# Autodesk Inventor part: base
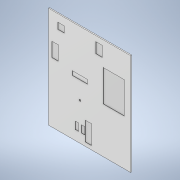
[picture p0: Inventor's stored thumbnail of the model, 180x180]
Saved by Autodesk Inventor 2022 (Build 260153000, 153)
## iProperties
Created: 2021-06
Part Number: base
Material: PC/ABS Plastic
Document SubType Name: Modeling
Designer: Chimms
Density: 0.357273 g/cm^3
Appearance: Smooth - White
Author: Chimms
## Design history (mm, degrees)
sketch "Sketch1"
  geometry: L1 (0, 0)-(150, 0); L2 (150, 0)-(150, -420); L3 (150, -420)-(0, -420); L4 (0, -420)-(0, 0)
  constraints: 8 end point, 2 parallel, 1 horizontal, 1 perpendicular
  dimensions: "d0" = 150 distance of L2.end L3.end; "d1" = 420 distance of L1.end L2.end
extrude "Extrusion1" new body sketch "Sketch1" distance "d2" = 5; taper "d3" = 0 deg
sketch "Sketch2"
  geometry: L1 (150, 0)-(0, 0) reference; L2 (150, 0)-(200, 0); L3 (200, 0)-(200, -420); L4 (200, -420)-(150, -420); L5 (150, -420)-(150, 0)
  constraints: 8 end point, 2 parallel, 1 horizontal, 1 perpendicular
  dimensions: "d4" = 50 distance of L3.end L4.end
extrude "Extrusion2" join sketch "Sketch2" distance "d5" = 5; taper "d6" = 0 deg
sketch "Sketch3"
  geometry: L1 (200, -420)-(200, 0) reference; L2 (200, 0)-(230, 0); L3 (230, 0)-(230, -420); L4 (230, -420)-(200, -420); L5 (200, -420)-(200, 0); 2 further points
  constraints: 8 end point, 2 parallel, 1 horizontal, 1 perpendicular
  dimensions: "d7" = 30 distance of L3.end L4.end
extrude "Extrusion3" join sketch "Sketch3" distance "d8" = 5; taper "d9" = 0 deg
sketch "Sketch4"
  geometry: L1 (0, -420)-(230, -420) reference; L2 (115, -420)-(115, -360); L3 (115, -360)-(122.25, -360); L4 (122.25, -360)-(122.25, -350); L5 (122.25, -350)-(132.25, -350); L6 (132.25, -350)-(142.25, -350); L7 (142.25, -350)-(142.25, -370); L8 (142.25, -370)-(122.25, -370); L9 (122.25, -370)-(122.25, -360); L10 (115, -360)-(107.75, -360); L11 (107.75, -360)-(107.75, -370); L12 (107.75, -370)-(87.75, -370); L13 (87.75, -370)-(87.75, -350); L14 (87.75, -350)-(107.75, -350); L15 (107.75, -350)-(107.75, -360); 1 further point
  constraints: 28 end point, 7 perpendicular, 5 point on line, 2 horizontal, 1 midpoint, 1 vertical
  dimensions: "d10" = 60 distance of L2.start L2.end; "d11" = 7.25 distance of L2.end L3.end; "d12" = 10 distance of L3.end L4.end; "d13" = 10 distance of L4.end L5.end; "d14" = 10 distance of L5.end L6.end; "d15" = 20 distance of L6.end L7.end; "d16" = 7.25 distance of L2.end L10.end; "d17" = 10 distance of L10.end L11.end; "d18" = 20 distance of L11.end L12.end
extrude "Extrusion4" cut sketch "Sketch4" distance "d19" = 2; taper "d20" = 0 deg
sketch "Sketch5"
  geometry: L1 (0, -420)-(230, -420) reference; L2 (115, -420)-(115, -220); L3 (115, -220)-(151, -220); L4 (151, -220)-(151, -200); L5 (151, -200)-(79, -200); L6 (79, -200)-(79, -220); L7 (79, -220)-(115, -220); 1 further point
  constraints: 12 end point, 3 perpendicular, 2 vertical, 1 midpoint
  dimensions: "d21" = 200 distance of L2.start L2.end; "d22" = 36 distance of L2.end L3.end; "d23" = 20 distance of L3.end L4.end; "d24" = 72 distance of L4.end L5.end; "d25" = 20 distance of L5.end L6.end
extrude "Extrusion5" cut sketch "Sketch5" distance "d26" = 2; taper "d27" = 0 deg
sketch "Sketch6"
  geometry: L1 (79, -200)-(151, -200) reference; L2 (115, -200)-(115, -50); L3 (230, 0)-(0, 0) reference; L4 (115, -50)-(190, -50); L5 (190, -50)-(190, -75); L6 (190, -75)-(220, -75); L7 (220, -75)-(220, -25); L8 (220, -25)-(190, -25); L9 (190, -25)-(190, -50); L10 (115, -50)-(40, -50); L11 (40, -50)-(40, -65); L12 (40, -65)-(10, -65); L13 (10, -65)-(10, -35); L14 (10, -35)-(40, -35); L15 (40, -35)-(40, -50)
  constraints: 26 end point, 12 perpendicular, 3 point on line, 1 midpoint
  dimensions: "d28" = 150 distance of L2.start L2.end; "d29" = 75 distance of L2.end L4.end; "d30" = 25 distance of L4.end L5.end; "d31" = 30 distance of L5.end L6.end; "d32" = 50 distance of L6.end L7.end; "d33" = 75 distance of L2.end L10.end; "d34" = 15 distance of L10.end L11.end; "d35" = 30 distance of L11.end L12.end; "d36" = 30 distance of L12.end L13.end
extrude "Extrusion6" cut sketch "Sketch6" distance "d37" = 2; taper "d38" = 0 deg
sketch "Sketch7"
  geometry: L1 (0, 0)-(0, -420) reference; L2 (0, 0)-(-35, 0); L3 (-35, 0)-(-35, -420); L4 (-35, -420)-(0, -420); L5 (0, -420)-(0, 0); 1 further point
  constraints: 8 end point, 2 parallel, 1 horizontal, 1 perpendicular
  dimensions: "d39" = 35 distance of L4.end L3.end
extrude "Extrusion7" join sketch "Sketch7" distance "d40" = 5; taper "d41" = 0 deg
sketch "Sketch8"
  geometry: L1 (-35, 0)-(230, 0) reference; L2 (230, 0)-(275, 0); L3 (275, 0)-(275, -420); L4 (275, -420)-(230, -420); L5 (230, -420)-(230, 0); 1 further point
  constraints: 8 end point, 2 parallel, 1 horizontal, 1 perpendicular
  dimensions: "d42" = 45 distance of L3.end L4.end; "d43" = 420 distance of L2.end L3.end
extrude "Extrusion8" join sketch "Sketch8" distance "d44" = 5; taper "d45" = 0 deg
sketch "Sketch9"
  geometry: L1 (275, -420)-(-35, -420) reference; L2 (275, -420)-(325, -420); L3 (325, -420)-(325, 0); L4 (325, 0)-(275, 0); L5 (275, 0)-(275, -420); 1 further point
  constraints: 8 end point, 2 parallel, 1 horizontal, 1 perpendicular
  dimensions: "d46" = 50 distance of L4.end L3.end
extrude "Extrusion9" join sketch "Sketch9" distance "d47" = 5; taper "d48" = 0 deg
sketch "Sketch10"
  geometry: L1 (325.31, -263.749)-(225.31, -263.749); L2 (225.31, -263.749)-(225.31, -113.749); L3 (225.31, -113.749)-(325.31, -113.749); L4 (325.31, -113.749)-(325.31, -263.749); L5 (325, 0)-(325, -420) reference; L6 (325, -420)-(355, -420); L7 (355, -420)-(355, 0); L8 (355, 0)-(325, 0); L9 (325, 0)-(325, -420); 3 further points
  constraints: 16 end point, 4 parallel, 2 horizontal, 2 perpendicular
  dimensions: "d49" = 100 distance of L2.end L3.end; "d50" = 150 distance of L1.end L2.end; "d51" = 30 distance of L8.end L7.end
extrude "Extrusion10" cut sketch "Sketch10" distance "d52" = 2; taper "d53" = 0 deg
sketch "Sketch11"
  geometry: L1 (325, 0)-(355, 0); L2 (355, 0)-(355, -420); L3 (355, -420)-(325, -420); L4 (325, -420)-(325, 0); 1 further point
  constraints: 8 end point, 2 parallel, 1 horizontal, 1 perpendicular
  dimensions: "d54" = 30 distance of L2.end L3.end
extrude "Extrusion11" join sketch "Sketch11" distance "d55" = 5; taper "d56" = 0 deg
sketch "Sketch12"
  geometry: L1 (151, -220)-(79, -220) reference; L2 (115, -220)-(115, -300); L3 (115, -300)-(118.5, -300); L4 (118.5, -300)-(118.5, -307); L5 (118.5, -307)-(111.5, -307); L6 (111.5, -307)-(111.5, -300); L7 (111.5, -300)-(115, -300); 1 further point
  constraints: 12 end point, 3 perpendicular, 2 vertical, 1 horizontal, 1 midpoint
  dimensions: "d59" = 80 distance of L2.start L2.end; "d60" = 3.5 distance of L2.end L3.end; "d61" = 7 distance of L3.end L4.end; "d62" = 7 distance of L4.end L5.end
extrude "Extrusion12" cut sketch "Sketch12" distance "d63" = 3; taper "d64" = 0 deg
sketch "Sketch13"
  geometry: L1 (107.75, -370)-(87.75, -370) reference; L2 (97.75, -370)-(97.75, -400); L3 (-35, -420)-(355, -420) reference; L4 (355, -420)-(-35, -420); L5 (-35, -420)-(-35, -450); L6 (-35, -450)-(355, -450); L7 (355, -450)-(355, -420); 2 further points
  constraints: 10 end point, 2 parallel, 1 horizontal, 1 midpoint, 1 perpendicular, 1 vertical
  dimensions: "d65" = 30 distance of L2.start L2.end; "d66" = 390 distance of L6.end L5.end; "d67" = 30 distance of L5.end L4.end
extrude "Extrusion13" join sketch "Sketch13" distance "d68" = 5; taper "d69" = 0 deg
sketch "Sketch14"
  geometry: L1 (107.75, -370)-(87.75, -370) reference; L2 (97.75, -370)-(97.75, -400); L3 (97.75, -400)-(107.75, -400); L4 (107.75, -400)-(107.75, -420); L5 (107.75, -420)-(87.75, -420); L6 (87.75, -420)-(87.75, -400); L7 (87.75, -400)-(97.75, -400); L8 (142.25, -370)-(122.25, -370) reference; L9 (132.25, -370)-(132.25, -400); L10 (132.25, -400)-(142.25, -400); L11 (142.25, -400)-(142.25, -420); L12 (142.25, -420)-(122.25, -420); L13 (122.25, -420)-(122.25, -400); L14 (122.25, -400)-(132.25, -400); 1 further point
  constraints: 24 end point, 10 perpendicular, 2 midpoint, 2 point on line, 2 vertical
  dimensions: "d70" = 30 distance of L2.start L2.end; "d71" = 20 distance of L3.end L4.end
extrude "Extrusion14" cut sketch "Sketch14" distance "d72" = 2; taper "d73" = 0 deg
sketch "Sketch15"
  geometry: L1 (107.75, -370)-(87.75, -370) reference; L2 (87.75, -350)-(107.75, -350) reference; L3 (87.75, -370)-(87.75, -350); L4 (87.75, -350)-(107.75, -350); L5 (107.75, -350)-(107.75, -370); L6 (107.75, -370)-(87.75, -370); L7 (122.25, -370)-(122.25, -350) reference; L8 (142.25, -350)-(142.25, -370) reference; L9 (122.25, -350)-(142.25, -350); L10 (142.25, -350)-(142.25, -370); L11 (142.25, -370)-(122.25, -370); L12 (122.25, -370)-(122.25, -350); 3 further points
  constraints: 16 end point, 4 perpendicular, 1 collinear, 1 horizontal, 1 point on line, 1 vertical
extrude "Extrusion15" join sketch "Sketch15" distance "d74" = 2; taper "d75" = 0 deg
sketch "Sketch16"
  geometry: L1 (122.25, -400)-(142.25, -400) reference; L2 (142.25, -400)-(157.25, -400); L3 (157.25, -400)-(157.25, -435); L4 (157.25, -435)-(122.25, -435); L5 (142.25, -420)-(122.25, -420) reference; L6 (122.25, -435)-(122.25, -420); L7 (107.75, -420)-(107.75, -435); L8 (107.75, -435)-(72.75, -435); L9 (72.75, -435)-(72.75, -400); L10 (87.75, -420)-(87.75, -400) reference; L11 (72.75, -400)-(87.75, -400); L12 (87.75, -400)-(107.75, -400) reference; L13 (87.75, -400)-(87.75, -420); L14 (122.25, -420)-(142.25, -420); L15 (142.25, -420)-(142.25, -400); 1 further point
  constraints: 22 end point, 7 perpendicular, 2 vertical, 1 collinear
  dimensions: "d76" = 15 distance of L1.end L2.end; "d77" = 35 distance of L2.end L3.end; "d78" = 35 distance of L7.end L8.end
extrude "Extrusion16" cut sketch "Sketch16" distance "d79" = 2; taper "d80" = 0 deg
sketch "Sketch17"
  geometry: L1 (107.75, -400)-(107.75, -420) reference; L2 (107.75, -420)-(107.75, -435); L3 (107.75, -435)-(72.75, -435); L4 (72.75, -435)-(72.75, -400); L5 (87.75, -400)-(107.75, -400) reference; L6 (72.75, -400)-(87.75, -400); L7 (87.75, -420)-(87.75, -400) reference; L8 (87.75, -400)-(87.75, -420); L9 (87.75, -420)-(107.75, -420); 1 further point
  constraints: 12 end point, 2 perpendicular, 2 vertical
  dimensions: "d81" = 15 distance of L1.end L2.end; "d82" = 35 distance of L2.end L3.end; "d83" = 35 distance of L3.end L4.end
extrude "Extrusion17" cut sketch "Sketch17" distance "d84" = 2; taper "d85" = 0 deg
sketch "Sketch18"
  geometry: L1 (157.25, -435)-(122.25, -435) reference; L2 (122.25, -400)-(157.25, -400) reference; L3 (157.25, -435)-(137.25, -435); L4 (137.25, -435)-(137.25, -400); L5 (137.25, -400)-(157.25, -400); L6 (157.25, -400)-(157.25, -435); L7 (72.75, -435)-(72.75, -400) reference; L8 (72.75, -400)-(107.75, -400) reference; L9 (72.75, -435)-(92.75, -435); L10 (92.75, -435)-(92.75, -400); L11 (92.75, -400)-(72.75, -400); L12 (72.75, -400)-(72.75, -435); 3 further points
  constraints: 16 end point, 4 parallel, 2 horizontal, 2 perpendicular, 2 point on line
  dimensions: "d86" = 20 distance of L4.end L5.end; "d87" = 20 distance of L11.end L10.end
extrude "Extrusion18" join sketch "Sketch18" distance "d88" = 2; taper "d89" = 0 deg
sketch "Sketch19"
  geometry: L1 (-17.763, -191.141)-(-17.763, -127.141); L2 (-17.763, -127.141)-(12.237, -127.141); L3 (12.237, -127.141)-(12.237, -195.141); L4 (-17.763, -191.141)-(-17.763, -195.141); L5 (-17.763, -195.141)-(12.237, -195.141); 1 further point
  constraints: 10 end point, 3 perpendicular, 2 vertical
  dimensions: "d90" = 64 distance of L1.start L1.end; "d91" = 30 distance of L1.end L2.end; "d92" = 68 distance of L2.end L3.end
extrude "Extrusion19" cut sketch "Sketch19" distance "d93" = 2; taper "d94" = 0 deg
sketch "Sketch20"
  geometry: L1 (143.042, -419.127)-(143.042, -359.127); L2 (143.042, -359.127)-(160.042, -359.127); L3 (160.042, -359.127)-(160.042, -419.127); L4 (160.042, -419.127)-(143.042, -419.127); 1 further point
  constraints: 8 end point, 3 perpendicular, 1 vertical
  dimensions: "d95" = 60 distance of L1.start L1.end; "d96" = 17 distance of L1.end L2.end
extrude "Extrusion20" cut sketch "Sketch20" distance "d97" = 2; taper "d98" = 0 deg
sketch "Sketch21"
  geometry: L1 (143.042, -419.127)-(143.042, -359.127) reference; L2 (160.042, -359.127)-(160.042, -419.127) reference; L3 (143.042, -359.127)-(160.042, -359.127); L4 (160.042, -359.127)-(160.042, -419.127); L5 (160.042, -419.127)-(143.042, -419.127); L6 (143.042, -419.127)-(143.042, -359.127); 3 further points
  constraints: 8 end point, 2 parallel, 1 horizontal, 1 perpendicular
extrude "Extrusion21" join sketch "Sketch21" distance "d99" = 2; taper "d100" = 0 deg
sketch "Sketch22"
  geometry: L1 (137.25, -435)-(137.25, -400) reference; L2 (137.25, -417.5)-(140.25, -417.5); L3 (122.25, -435)-(122.25, -400) reference; L4 (140.25, -417.5)-(140.25, -372.5); L5 (140.25, -372.5)-(170.25, -372.5); L6 (-35, -450)-(355, -450); L7 (355, -450)-(355, -480); L8 (355, -480)-(-35, -480); L9 (-35, -480)-(-35, -450); 1 further point
  constraints: 14 end point, 4 perpendicular, 2 parallel, 1 horizontal, 1 midpoint
  dimensions: "d101" = 3 distance of L2.start L2.end; "d102" = 45 distance of L2.end L4.end; "d103" = 30 distance of L4.end L5.end; "d104" = 390 distance of L7.end L8.end; "d105" = 30 distance of L6.end L7.end
extrude "Extrusion22" join sketch "Sketch22" distance "d106" = 5; taper "d107" = 0 deg
sketch "Sketch23"
  geometry: L1 (137.25, -435)-(137.25, -400) reference; L2 (137.25, -417.5)-(140.25, -417.5); L3 (140.25, -417.5)-(140.25, -372.5); L4 (140.25, -372.5)-(170.25, -372.5); L5 (170.25, -372.5)-(170.25, -462.5); L6 (170.25, -462.5)-(140.25, -462.5); L7 (140.25, -462.5)-(140.25, -417.5); 1 further point
  constraints: 12 end point, 5 perpendicular, 1 horizontal, 1 midpoint, 1 point on line
  dimensions: "d108" = 3 distance of L2.start L2.end; "d109" = 45 distance of L2.end L3.end; "d110" = 30 distance of L3.end L4.end; "d111" = 90 distance of L4.end L5.end
extrude "Extrusion23" cut sketch "Sketch23" distance "d112" = 2; taper "d113" = 0 deg
body "Solid1"
